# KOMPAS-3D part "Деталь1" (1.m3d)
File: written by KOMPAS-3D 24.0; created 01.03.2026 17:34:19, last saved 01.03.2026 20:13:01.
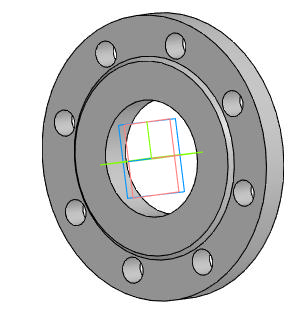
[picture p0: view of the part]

Document properties: Автор: R2D2; Полное имя файла: E:\Работа\Зайцев\GVWR3131M-2W-F-S Задвижка клиновая 30нж64нж DN.ru  Ду50-150 Ру25\исходные данные\DN80\1.m3d

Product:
- Part/product: Деталь1
    Масса: 3.627543
    additional columns: Типовые

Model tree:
1. Эскиз:2
2. Элемент вращения:1
     Угол 1 = 360
3. Эскиз:3  (with: Грань.Элемент вращения:1)
4. Элемент выдавливания:2
     Расстояние 2 = 19
5. Массив по концентрической сетке:1  (with: Элемент выдавливания:2, Эскиз:3, Грань.Элемент вращения:1)  (8 pattern instances)
     Шаг 2 = 360
6. Эскиз:4  (with: Грань.Элемент вращения:1)
7. Элемент выдавливания:3
     Расстояние 2 = 2.5

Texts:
  Линейный размер с обрывом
